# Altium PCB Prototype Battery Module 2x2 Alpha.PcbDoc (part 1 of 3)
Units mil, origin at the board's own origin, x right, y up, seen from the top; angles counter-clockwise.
Board outline 659.45 x 1614.17 mil, 6 copper layers (Component Side, Ground Plane (GND), Inner Layer 1, Inner Layer 2, Power Plane (VCC), Solder Side), stack 51.068 mil thick; 192 components, 101 nets, 859 pads, 497 vias.
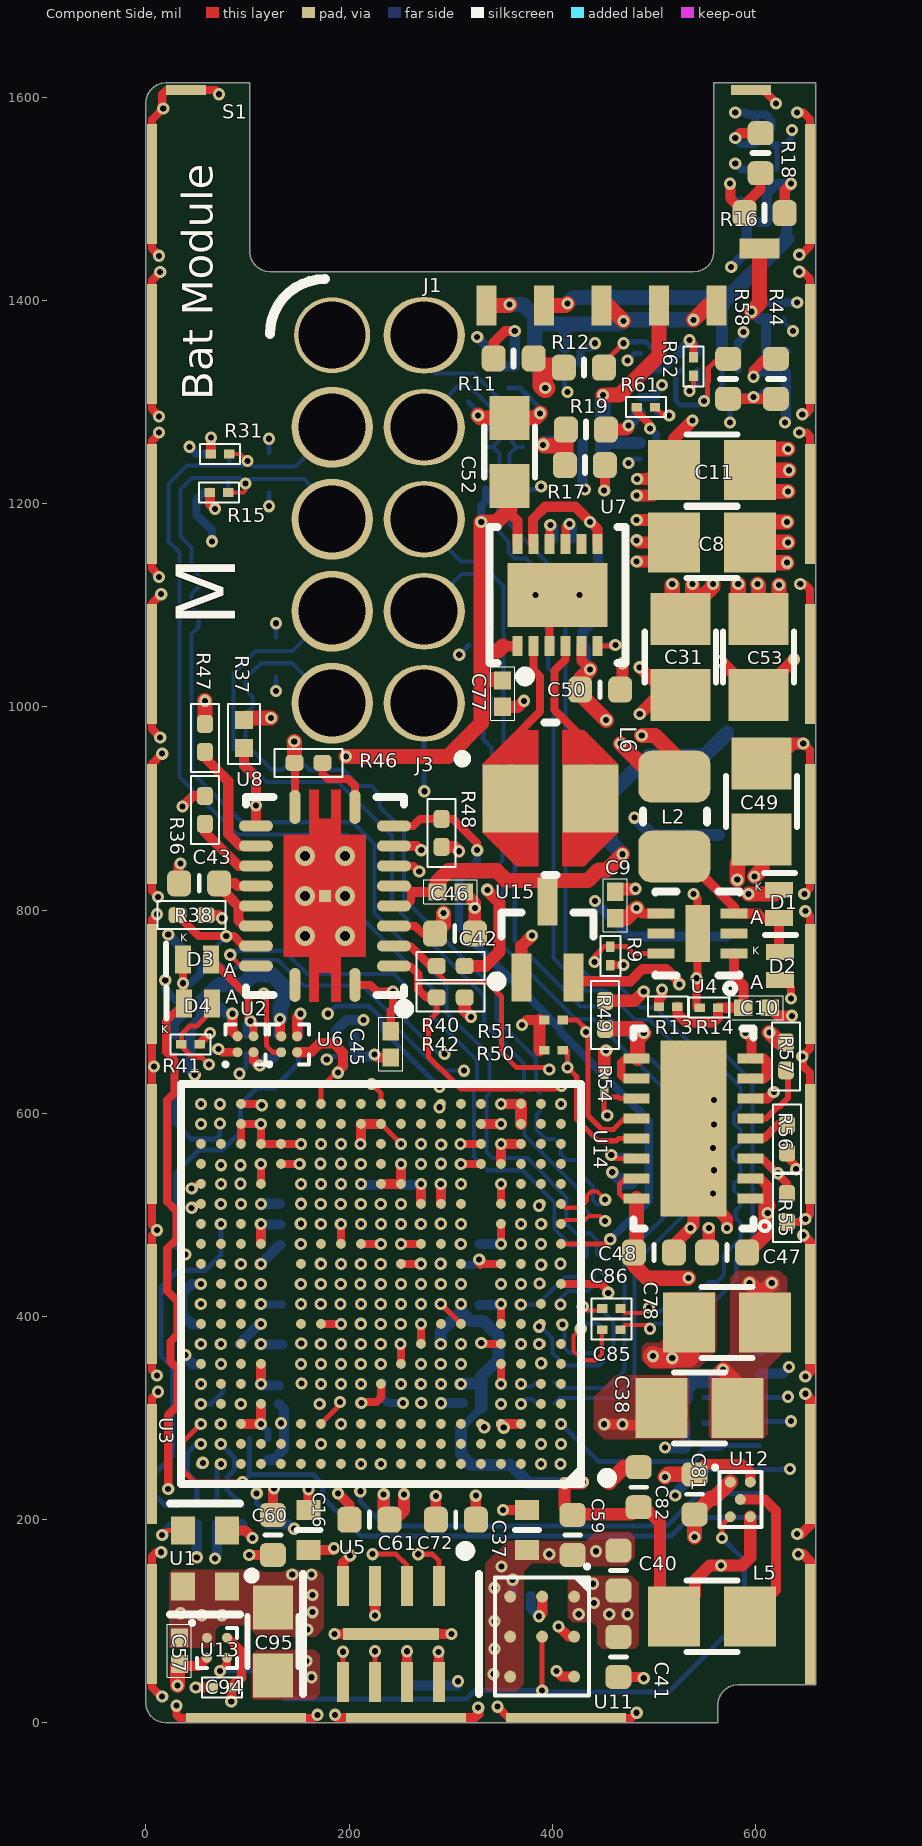
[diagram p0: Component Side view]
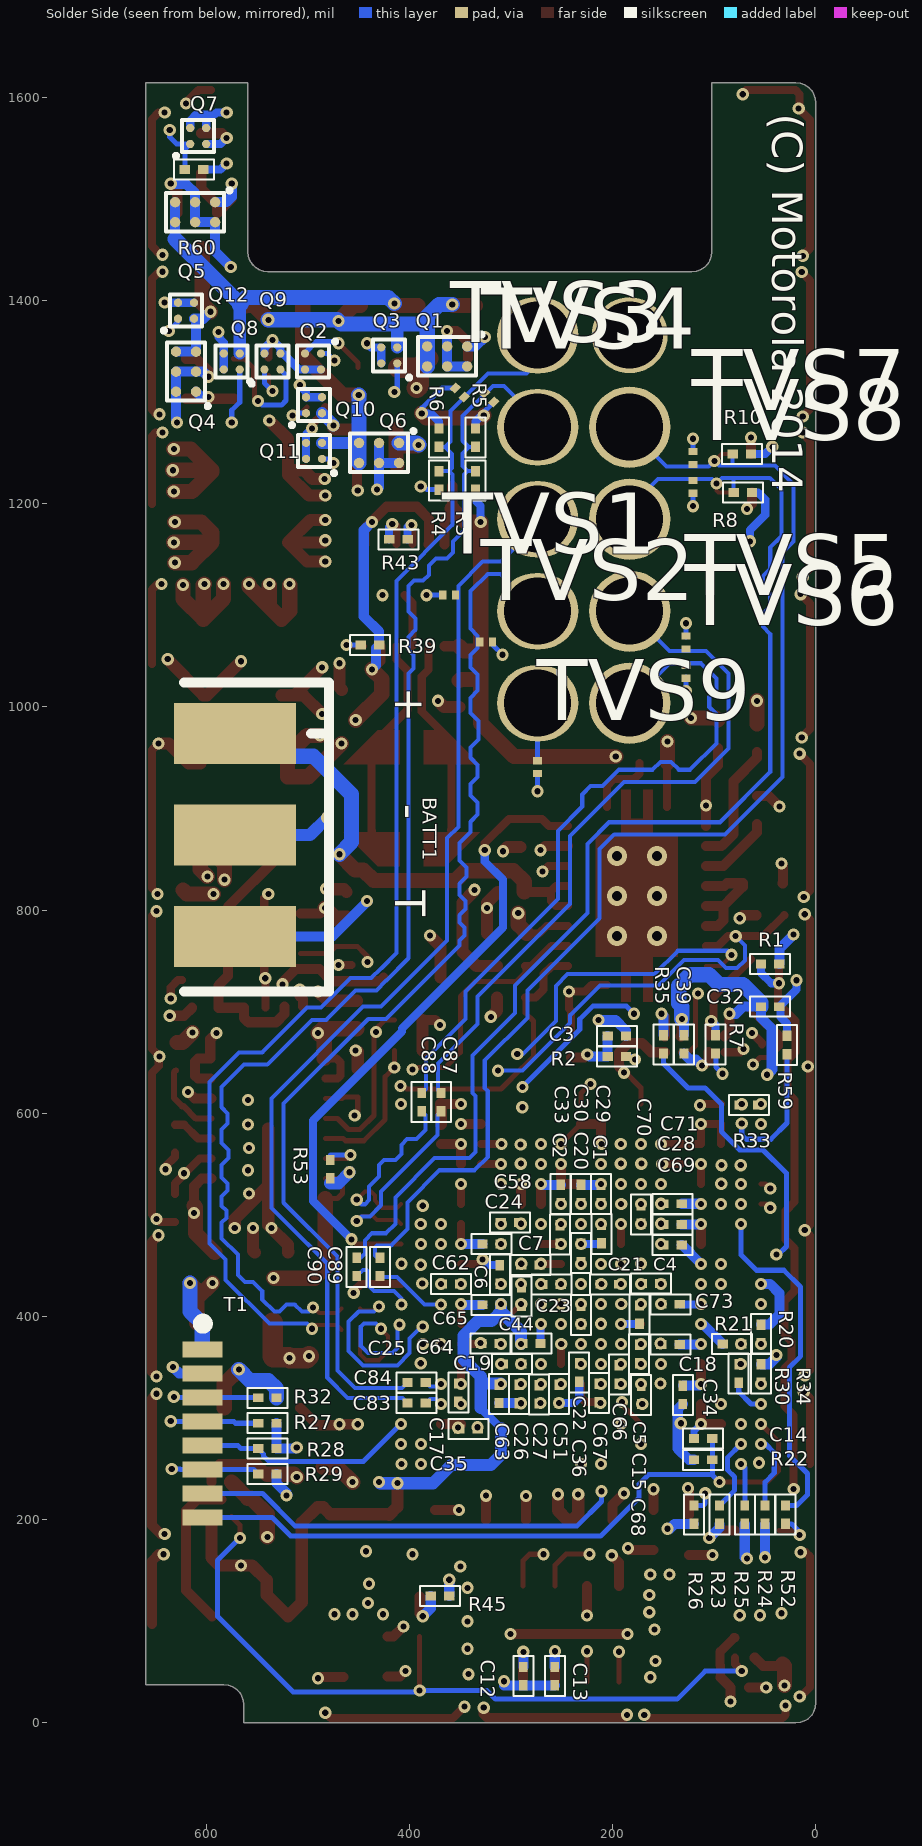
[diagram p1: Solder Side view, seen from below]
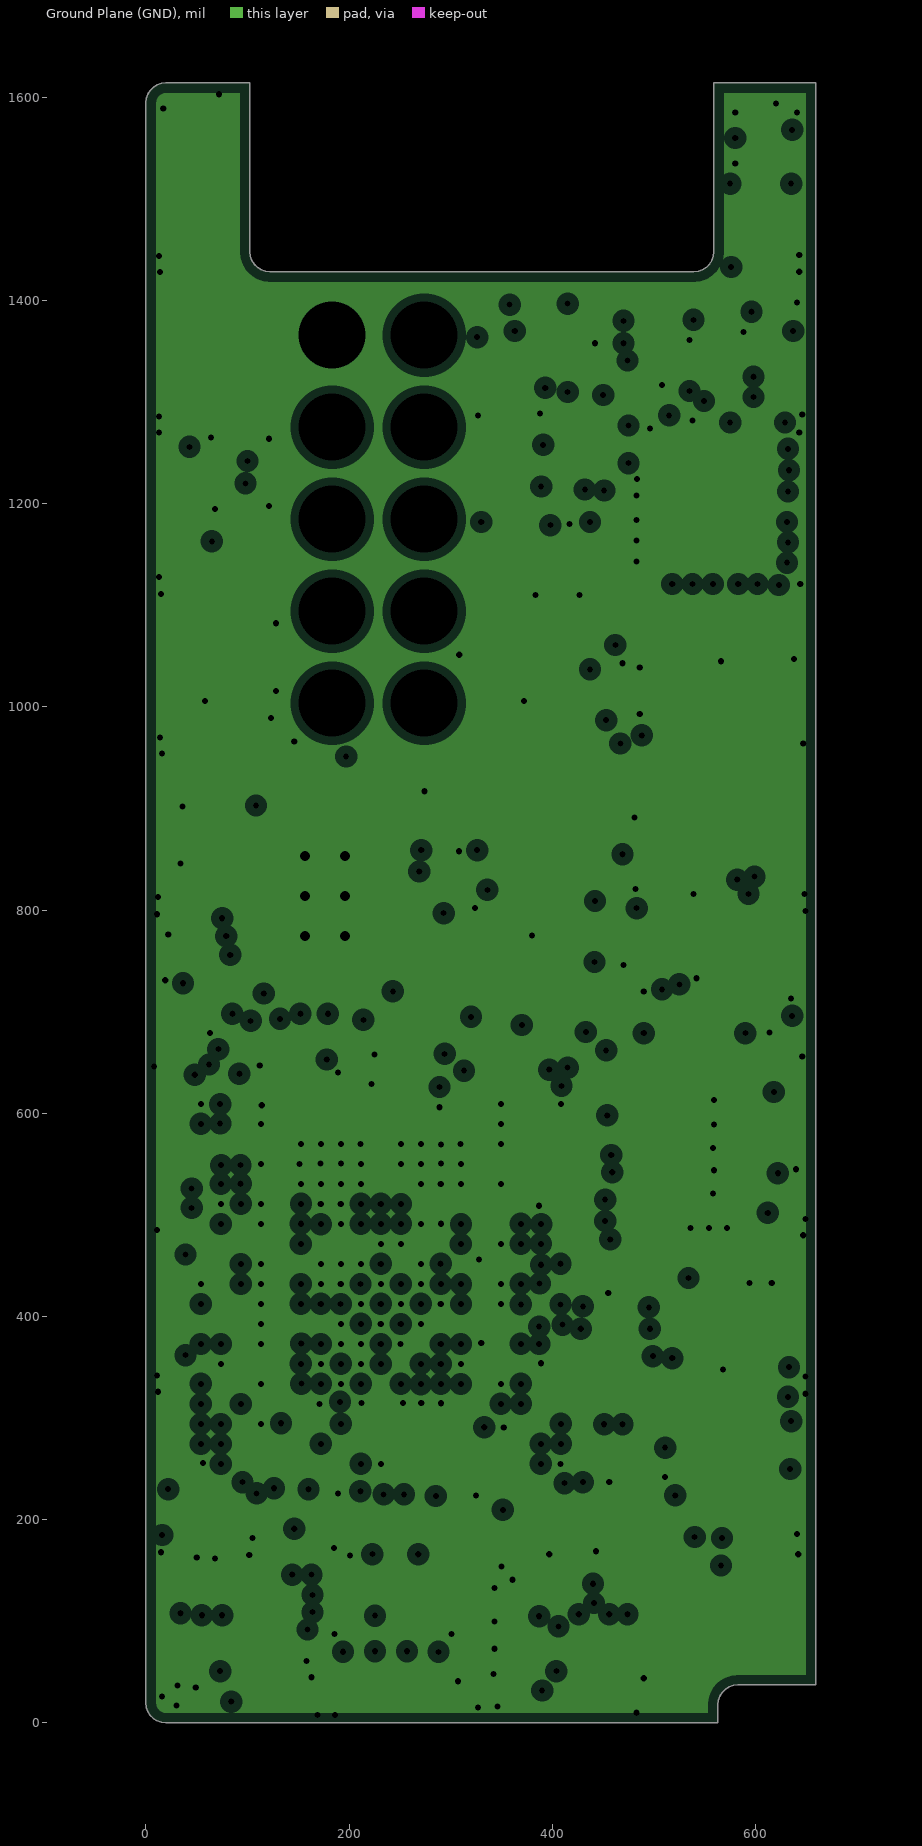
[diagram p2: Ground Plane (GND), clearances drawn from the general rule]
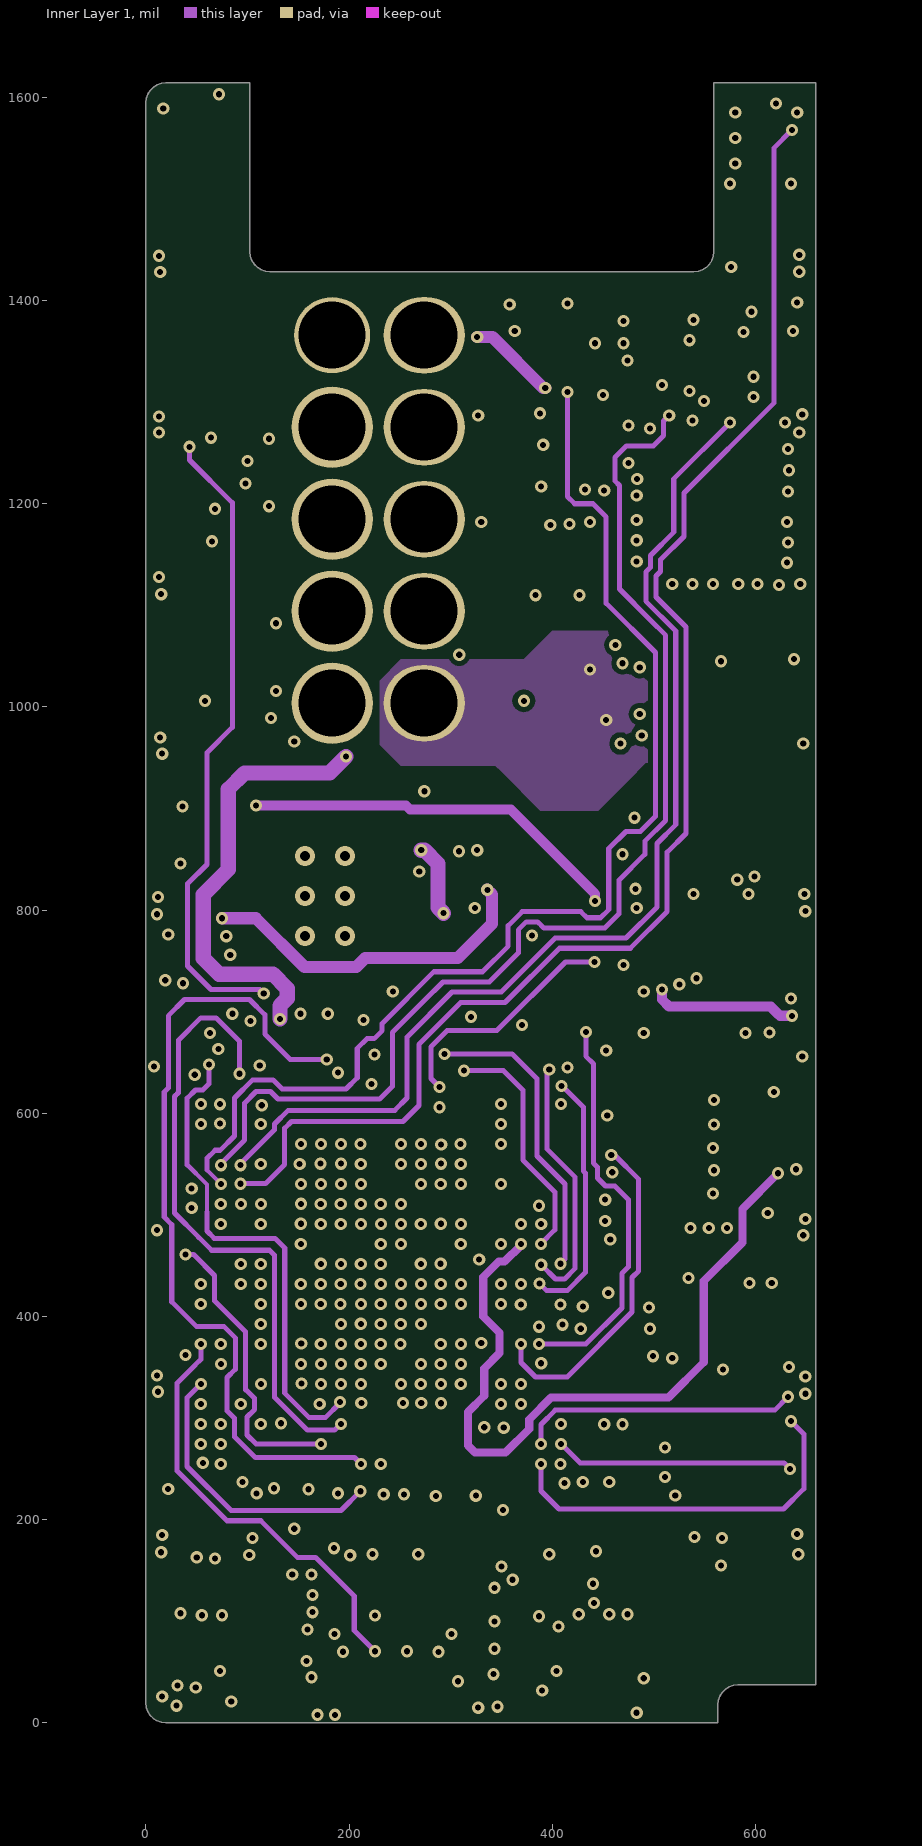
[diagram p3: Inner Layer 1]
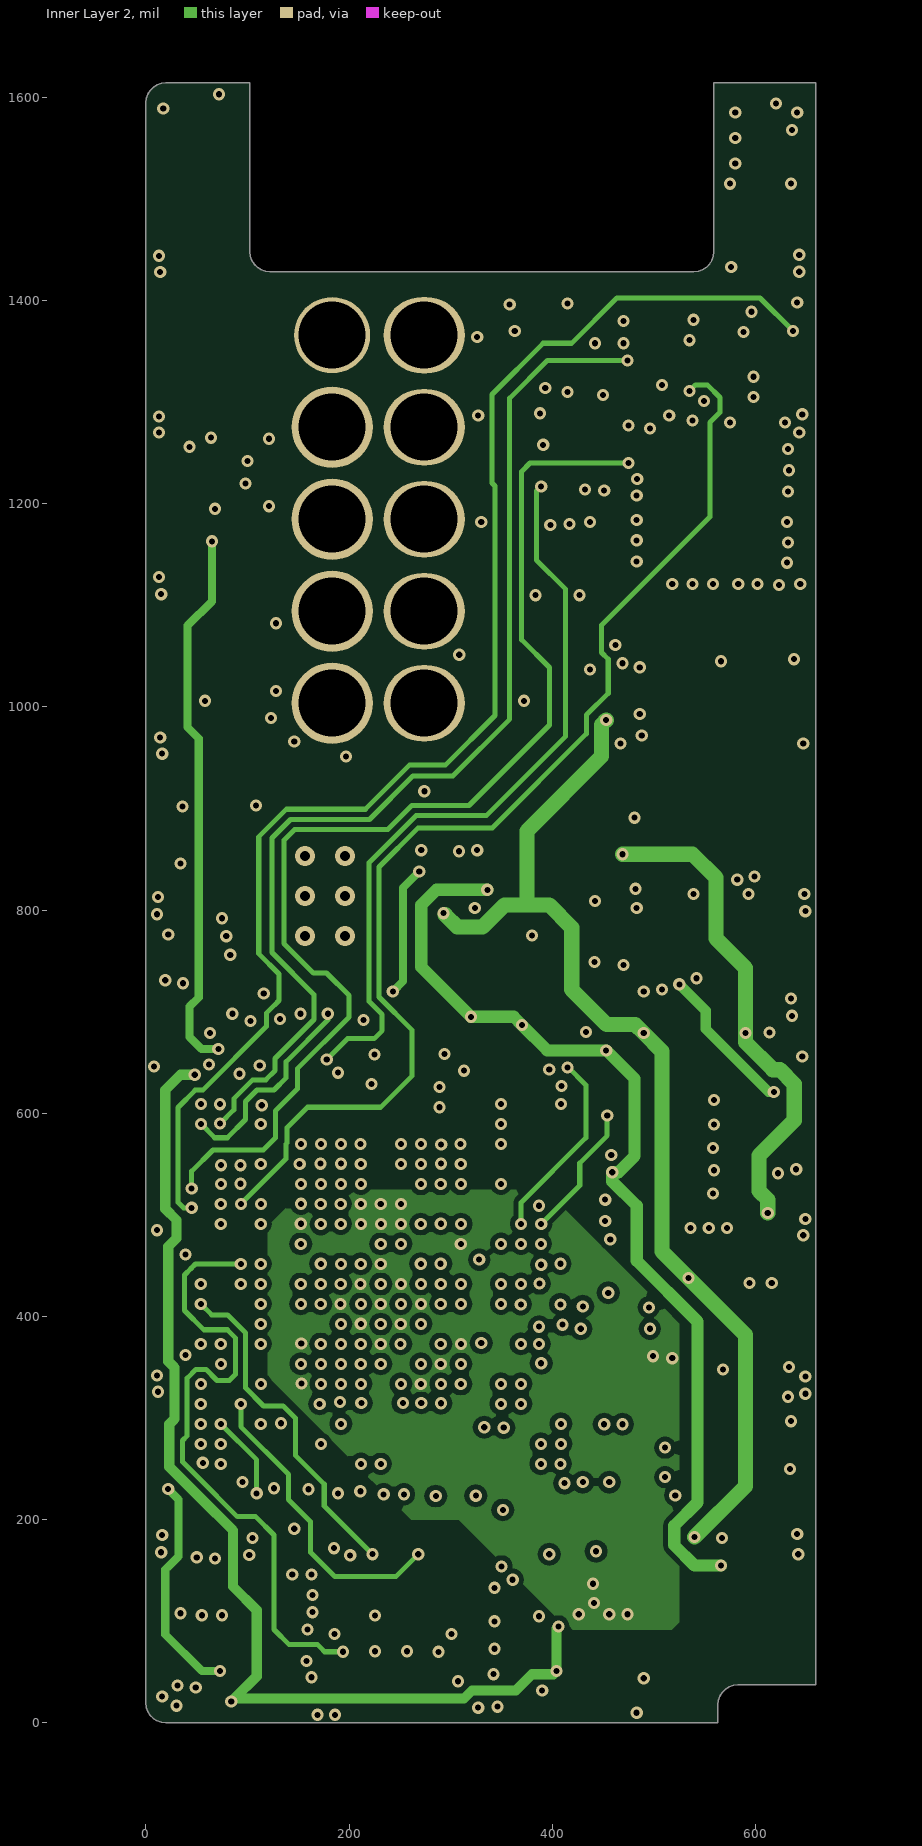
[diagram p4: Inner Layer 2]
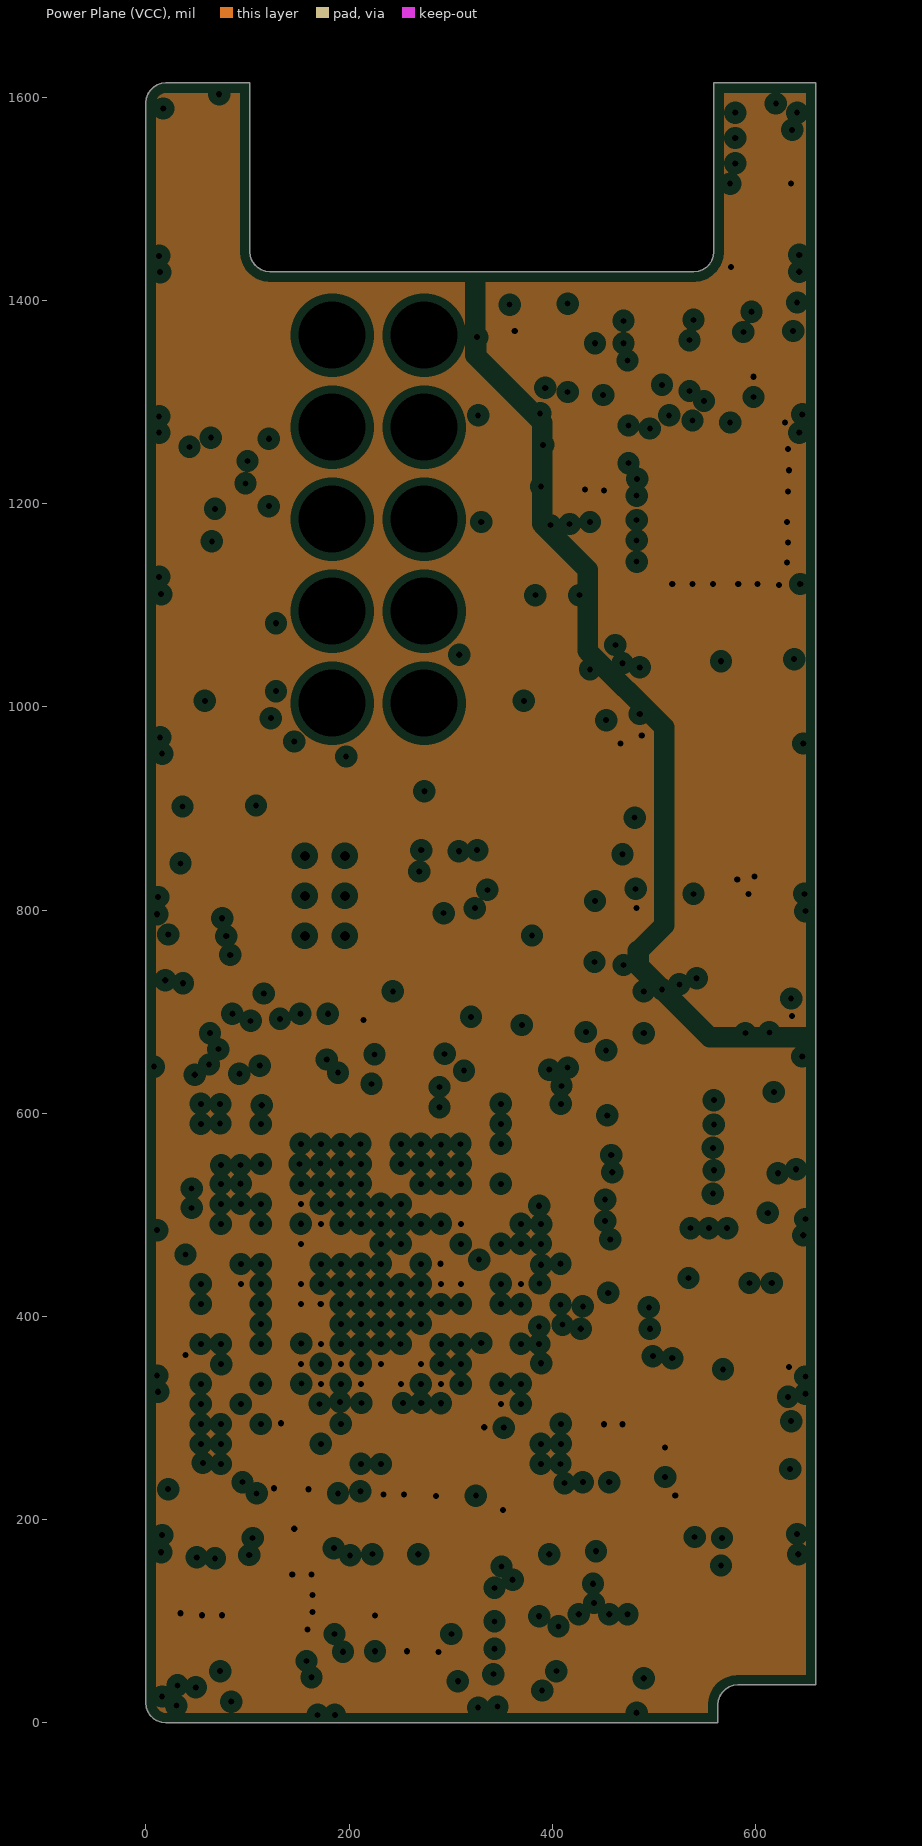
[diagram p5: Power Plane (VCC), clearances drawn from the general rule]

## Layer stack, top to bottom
Top Solder: solder mask 0.4, Solder Resist, Dk 3.5
Component Side: signal copper 1.4
Dielectric1: core 12.6, FR-4, Dk 4.8
Ground Plane (GND): plane copper 1.417, net GND
Dielectric4: prepreg 5, Dk 4.2
Inner Layer 1: signal copper 1.417
Dielectric2: core 10, Dk 4.2
Inner Layer 2: signal copper 1.417
Dielectric3: prepreg 5, Dk 4.2
Power Plane (VCC): plane copper 1.417, net (Multiple Nets)
Dielectric5: core 10, Dk 4.2
Solder Side: signal copper 1.4
Bottom Solder: solder mask 0.4, Solder Resist, Dk 3.5

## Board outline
582.68,37.4 659.45,37.4 659.45,1614.17 559.06,1614.17 559.06,1448.03 558.56,1443.65 557.11,1439.49 554.76,1435.76 551.64,1432.64 547.91,1430.3 543.75,1428.84 539.37,1428.35 122.05,1428.35 117.67,1428.84 113.51,1430.3 109.77,1432.64 106.66,1435.76 104.31,1439.49 102.86,1443.65 102.36,1448.03 102.36,1614.17 19.68,1614.17 15.3,1613.68 11.14,1612.22 7.41,1609.88 4.29,1606.76 1.95,1603.03 0.49,1598.87 0,1594.49 0,19.68 0.49,15.3 1.95,11.14 4.29,7.41 7.41,4.29 11.14,1.95 15.3,0.49 19.68,0 562.99,0 562.99,17.72 563.49,22.1 564.94,26.26 567.29,29.99 570.4,33.11 574.14,35.45 578.3,36.91

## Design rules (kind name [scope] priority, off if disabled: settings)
Clearance diff_1 [InNetClass('diff')] p1: gap=5
Clearance [All] p2: gap=5
DiffPairsRouting [All] p1: maxlimit=8 minlimit=8 mostfreqgap=8 toplayer_minwidth=15 toplayer_maxwidth=15 toplayer_prefwidth=15 midlayer1_minwidth=15 midlayer1_maxwidth=15 midlayer1_prefwidth=15 midlayer2_minwidth=15 midlayer2_maxwidth=15 midlayer2_prefwidth=15 bottomlayer_minwidth=15 bottomlayer_maxwidth=15 bottomlayer_prefwidth=15 maxuncoupledlength=500
FabricationTestPointUsage [All] p1 off: valid=0 allowmultiple=FALSE
FabricationTestpoint [(IsPad And (OnTopLayer Or OnBottomLayer))] p1 off: side=3 testpointundercomponent=TRUE minsize=40 maxsize=100 preferedsize=60 minholesize=0 maxholesize=40 preferedholesize=32 testpointgrid=1 allowsidetop=TRUE allowsidebottom=TRUE usegrid=TRUE gridtolerance=0.01
MatchedLengths DiffPair_MatchedLengths [InDifferentialPair ('SERDES_TX_CHIP')] p1: tolerance=1000 checknetsindiffpair=TRUE checkdiffpairvsdiffpair=TRUE checkothers=TRUE
MatchedLengths DiffPair_MatchedLengths_1 [InDifferentialPair ('SERDES_TX')] p2: tolerance=1000 checknetsindiffpair=TRUE checkdiffpairvsdiffpair=TRUE checkothers=TRUE
MatchedLengths DiffPair_MatchedLengths_2 [InDifferentialPair ('SERDES_RX')] p3: tolerance=1000 checknetsindiffpair=TRUE checkdiffpairvsdiffpair=TRUE checkothers=TRUE
MatchedLengths DiffPair_MatchedLengths_3 [InDifferentialPair ('RCLK_100MHZ')] p4: tolerance=1000 checknetsindiffpair=TRUE checkdiffpairvsdiffpair=TRUE checkothers=TRUE
MatchedLengths DiffPair_MatchedLengths_4 [InDifferentialPair ('OSC_100MHZ')] p5: tolerance=1000 checknetsindiffpair=TRUE checkdiffpairvsdiffpair=TRUE checkothers=TRUE
MinimumSolderMaskSliver [All] p1: minsoldermaskwidth=3
PlaneClearance [All] p1: clearance=8
PlaneConnect [All] p1: planeconnectstyle=Direct reliefexpansion=8 reliefentries=4 reliefconductorwidth=8 reliefairgap=8
PolygonConnect [All] p1: connectstyle=Direct reliefconductorwidth=10 reliefentries=4 polygonreliefangle="90 Angle" airgapwidth=10
RoutingVias [All] p1: holewidth=6 width=12 viastyle="Through Hole" minholewidth=6 minwidth=12 maxholewidth=6 maxwidth=12
SilkToSilkClearance [All] p1: silktosilkclearance=3
SilkToSolderMaskClearance [IsPad] p1: minsilkscreentomaskgap=3 clearancetoexposedcopper=TRUE
SolderMaskExpansion [All] p1: expansion=4
Width diff [InNetClass('diff')] p1: maxlimit=4 minlimit=4 preferedwidth=4
Width [All] p2: maxlimit=30 minlimit=4 preferedwidth=5
21 further rules are at their usual default settings.

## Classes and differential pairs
differential pair TX: +TX_P -TX_N
differential pair TX_CLK: +TX_CLK_P -TX_CLK_N
differential pair RX: +RX_P -RX_N
differential pair RX_CLK: +RX_CLK_P -RX_CLK_N
differential pair C_TX: +C_TX_P -C_TX_N
differential pair C_TX_CLK: +C_TX_CLK_P -C_TX_CLK_N
differential pair C_RX: +C_RX_P -C_RX_N
differential pair C_RX_CLK: +C_RX_CLK_P -C_RX_CLK_N

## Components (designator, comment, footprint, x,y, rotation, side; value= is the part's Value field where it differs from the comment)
BATT1 "J_BATT" 1X3_PADS 571.81,974 r270 bottom
C1 "0.1uF" C_01005 211,481 r90 bottom
C2 "0.1uF" C_01005 251.97,480.71 r90 bottom
C3 "0.1uF" C_01005 196,676 r180 bottom
C4 "0.1uF" C_01005 162.17,432.52 r180 bottom
C5 "0.1uF" C_01005 173.69,401.76 r90 bottom
C6 "0.1uF" C_01005 311.17,441.52 r270 bottom
C7 "0.1uF" C_01005 281.1,450.79 r0 bottom locked
C8 "22µF" C_ERA-0805 557,1162 r0 top
C9 "0.1UF" CAPC0201 462,805 r270 top
C10 "C_0201_22pF" CAPC0201 601,704 r0 top
C11 "22µF" C_ERA-0805 557,1233 r0 top
C12 "0.1uF" C_01005 288,46 r270 bottom
C13 "0.1uF" C_01005 257,46 r270 bottom
C14 "0.1uF" C_01005 111,280 r0 bottom
C15 "0.1uF" C_01005 174,363 r270 bottom
C16 "1.0uF" C_ERA-0402 160,190 r90 top
C17 "0.1uF" C_01005 352,325 r90 bottom
C18 "0.1uF" C_01005 143.17,372.52 r0 bottom
C19 "0.1uF" C_01005 299.24,353.35 r180 bottom
C20 "0.1uF" C_01005 231.17,462.52 r270 bottom
C21 "0.1uF" C_01005 202.69,431.76 r0 bottom
C22 "0.1uF" C_01005 231.17,401.52 r90 bottom
C23 "0.1uF" C_01005 260.17,431.52 r180 bottom
C24 "0.1uF" C_01005 319.17,471.52 r180 bottom
C25 "0.1uF" C_01005 320.17,373.52 r180 bottom
C26 "0.1uF" C_01005 292.32,323.68 r90 bottom
C27 "0.1uF" C_01005 272.55,323.43 r90 bottom
C28 "0.1uF" C_01005 141.17,490.52 r0 bottom
C29 "0.1uF" C_01005 211.67,520.52 r270 bottom
C30 "0.1uF" C_01005 231.17,520.52 r270 bottom
C31 "22µF" C_ERA-0805 526,1049 r90 top
C32 "0.1uF" C_01005 45,705 r0 bottom
C33 "0.1uF" C_01005 251.17,520.52 r270 bottom
C34 "0.1uF" C_01005 131,323 r270 bottom
C35 "0.1uF" C_01005 342.1,289.3 r180 bottom
C36 "0.1uF" C_01005 233,345 r90 bottom
C37 "1.0uF" C_ERA-0402 375,190 r90 top
C38 "22uF" C_ERA-0805 545,310 r180 top
C39 "0.1uF" C_01005 130,668 r90 bottom
C40 "10uF" C_0402 465,150 r270 top
C41 "1uF" C_0402 465,65 r90 top
C42 "C_0402_10uF" C_0402 304,777 r180 top
C43 "C_0402_10uF" C_0402 52.4,826.4 r0 top
C44 "0.1uF" C_01005 289.69,419.76 r90 bottom
C45 "1uF" CAPC0201 241,668 r90 top
C46 "1uF" CAPC0201 300,818 r180 top
C47 "C_0402_10uF" C_0402 572,463 r0 top
C48 "C_0402_10uF" C_0402 500,463 r180 top
C49 "22µF" C_ERA-0805 606,907 r270 top
C50 "10uF" C_0402 447,1017 r180 top
C51 "0.1uF" C_01005 253,324 r90 bottom
C52 "22uF" C_ERA-0603 358,1251 r270 top
C53 "22µF" C_ERA-0805 603,1049 r90 top
C57 "0.47µF" CAPC0201 33,71 r90 top
C58 "0.1uF" C_01005 301.17,492.52 r0 bottom
C59 "10uF" C_0402 420,185 r90 top
C60 "10uF" C_0402 125,185 r90 top
C61 "10uF" C_0402 220,200 r0 top
C62 "0.1uF" C_01005 359,432 r0 bottom
C63 "0.1uF" C_01005 312,324 r90 bottom
C64 "0.1uF" C_01005 280.17,373.52 r0 bottom
C65 "0.1uF" C_01005 319.17,411.52 r180 bottom
C66 "0.1uF" C_01005 194,343 r90 bottom
C67 "0.1uF" C_01005 213.58,324.69 r90 bottom
C68 "0.1uF" C_01005 172,323 r90 bottom
C69 "0.1uF" C_01005 141.17,470.52 r0 bottom
C70 "0.1uF" C_01005 172.17,500.52 r270 bottom
C71 "0.1uF" C_01005 141,511 r0 bottom
C72 "10uF" C_0402 305,200 r180 top
C73 "0.1uF" C_01005 143,412 r0 bottom
C77 "0.47µF" CAPC0201 351,1013 r90 top
C78 "22uF" C_ERA-0805 572,394 r180 top
C81 "4.7uF" C_0402 540,225 r270 top
C82 "10uF" C_0402 485,232 r270 top
C83 "0.1uF" C_01005 393,315 r180 bottom
C84 "0.1uF" C_01005 393,335 r180 bottom
C85 "0.1uF" C_01005 458,387 r180 top
C86 "0.1uF" C_01005 458,408 r180 top
C87 "0.1uF" C_01005 369,611 r270 bottom
C88 "0.1uF" C_01005 388,611 r270 bottom
C89 "0.1uF" C_01005 429,449 r270 bottom
C90 "0.1uF" C_01005 452,449 r270 bottom
C94 "0.1uF" C_01005 75,35 r0 top
C95 "22uF" C_ERA-0603 125,80 r90 top
D1 "SBR0240LP-7" 2-XFDFN 623,806 r270 top
D2 "SBR0240LP-7" 2-XFDFN 624,745 r270 top
D3 "SBR0240LP-7" 2-XFDFN 50.2,751.61 r0 top
D4 "SBR0240LP-7" 2-XFDFN 51,708 r0 top
J1 "EPM" EPM_3X_CONNECTION 335,1395 r90 top
J3 "SPRING PIN" "10PIN SMD CONNECTOR" 273.86,1003.7 r90 top locked
L2 "CBC2016T220K" L_0806 520,892 r90 top
L5 "2.2uH" C_ERA-0805 557,105 r180 top
L6 "2.2uH Wirewound" L_SMD_2.2uH 398,910 r180 top
Q1 "SI8497DB-T2-E1" BGA6C50P3X2_145X96X59 363,1345 r0 bottom
Q2 "SI8808DB-T2-E1" BGA4C40P2X2_80X80X40 495,1340 r0 bottom
Q3 "SI8808DB-T2-E1" BGA4C40P2X2_80X80X40 420,1346 r90 bottom
Q4 "SI8497DB-T2-E1" BGA6C50P3X2_145X96X59 620,1330 r90 bottom
Q5 "SI8497DB-T2-E1" BGA6C50P3X2_145X96X59 611,1487 r0 bottom
Q6 "SI8497DB-T2-E1" BGA6C50P3X2_145X96X59 430,1250 r0 bottom
Q7 "SI8808DB-T2-E1" BGA4C40P2X2_80X80X40 608,1562 r180 bottom
Q8 "SI8808DB-T2-E1" BGA4C40P2X2_80X80X40 575,1340 r90 bottom
Q9 "SI8808DB-T2-E1" BGA4C40P2X2_80X80X40 535,1340 r180 bottom
Q10 "SI8808DB-T2-E1" BGA4C40P2X2_80X80X40 494,1297 r180 bottom
Q11 "SI8808DB-T2-E1" BGA4C40P2X2_80X80X40 494,1252 r90 bottom
Q12 "SI8808DB-T2-E1" BGA4C40P2X2_80X80X40 620,1390 r180 bottom
R1 "1M Ohms" R_01005#1 45,747 r180 bottom
R2 "1k" R_01005#1 196,656 r180 bottom
R3 "10K" R_01005#1 335,1223 r270 bottom
R4 "10K" R_01005#1 371,1223 r270 bottom
R5 "1M Ohms" R_01005#1 335,1265 r90 bottom
R6 "1M Ohms" R_01005#1 371,1265 r90 bottom
R7 "10K" R_01005#1 99,668 r270 bottom
R8 "10K" R_01005#1 71.94,1211 r180 bottom
R9 "1k" R_01005#1 457,755 r270 top
R10 "10K" R_01005#1 72.94,1249 r180 bottom
R11 "270" R_0402 362,1343 r0 top
R12 "100" R_0402 431,1334 r0 top
R13 "10K" R_01005#1 514,705 r0 top
R14 "4.7k" R_01005#1 554,704 r180 top
R15 "1M Ohms" R_01005#1 71.94,1211 r180 top
R16 "270" R_0402 609,1486 r180 top
R17 "270" R_0402 432,1238 r180 top
R18 "100" R_0402 605,1545 r90 top
R19 "100" R_0402 433,1273 r0 top
R20 "1k" R_01005#1 54,383 r270 bottom
R21 "1k" R_01005#1 82.76,373.03 r0 bottom
R22 "10K" R_01005#1 111,259 r180 bottom
R23 "10K" R_01005#1 95,205 r270 bottom
R24 "10K" R_01005#1 50,205 r270 bottom
R25 "10K" R_01005#1 70,205 r270 bottom
R26 "10K" R_01005#1 120,205 r270 bottom
R27 "4.7k" R_01005#1 540,295 r0 bottom
R28 "4.7k" R_01005#1 540,270 r0 bottom
R29 "4.7k" R_01005#1 540,245 r0 bottom
R30 "10K" R_01005#1 76,344 r90 bottom
R31 "1M Ohms" R_01005#1 72.94,1249 r180 top
R32 "4.7k" R_01005#1 540,320 r180 bottom
R33 "10K" R_01005#1 65.91,608.35 r180 bottom
R34 "10K" R_01005#1 54,344 r90 bottom
R35 "10K" R_01005#1 150,668 r270 bottom
R36 "51K" R_0201 58.07,898.62 r90 top
R37 "10K" R0201 96.46,973.43 r90 top
R38 "R_0201_100k" R_0201 45,795 r180 top
R39 "10K" R_01005#1 439,1061 r0 bottom
R40 "R_0201_100k" R_0201 300,745 r180 top
R41 "10K" R_01005#1 44,668 r180 top
R42 "R_0201_100k" R_0201 300,714 r180 top
R43 "10K" R_01005#1 411,1165 r180 bottom
R44 "270" R_0402 620,1323 r270 top
R45 "10K" R_01005#1 370,125 r0 bottom
R46 "3.3K" R_0201 160,945 r180 top
R47 "0 Ohms" R_0201 58.07,969.49 r90 top
R48 "R_0201_100k" R_0201 291,876 r270 top
R49 "R_0201_100k" R_0201 452,697 r90 top
R50 "100K" R_01005#2 401,662 r0 top
R51 "100K" R_01005#2 401,692 r0 top
R52 "33" R_01005#1 30,205 r90 bottom
R53 "100K" R_01005#2 478,545 r90 bottom
R54 "100K" R_01005#2 451,630 r270 top
R55 "R_0201_100k" R_0201 631,507 r270 top
R56 "R_0201_510" R_0201 631,575 r270 top
R57 "1K" R_0201 630,656 r90 top
R58 "100" R_0402 573,1323 r90 top
R59 "1k" R_01005#1 28.54,667.32 r90 bottom
R60 "1k" R_01005#1 612,1529 r180 bottom
R61 "1k" R_01005#1 492,1295 r180 top
R62 "1k" R_01005#1 539,1335 r90 top
S1 "RFSHIELD" RFSHIELD_BATMODULE 0,-0.98 r0 top locked
T1 "8 PIN TEST_INTERFACE" "8-PIN TEST INTERFACE" 604,285 r180 bottom
TVS1 "TVS_ESDAVLC6-1BV2" ST_MICRO_TVS 361,1110 r0 bottom
TVS2 "TVS_ESDAVLC6-1BV2" ST_MICRO_TVS 324.61,1064 r180 bottom
TVS3 "TVS_ESDAVLC6-1BV2" ST_MICRO_TVS 350.55,1309.55 r45 bottom
TVS4 "TVS_ESDAVLC6-1BV2" ST_MICRO_TVS 321.64,1304.64 r225 bottom
TVS5 "TVS_ESDAVLC6-1BV2" ST_MICRO_TVS 128,1063.39 r90 bottom
TVS6 "TVS_ESDAVLC6-1BV2" ST_MICRO_TVS 128,1034.61 r270 bottom
TVS7 "TVS_ESDAVLC6-1BV2" ST_MICRO_TVS 121,1245 r90 bottom
TVS8 "TVS_ESDAVLC6-1BV2" ST_MICRO_TVS 121,1216.61 r270 bottom
TVS9 "TVS_ESDAVLC6-1BV2" ST_MICRO_TVS 273.86,940.75 r270 bottom
U1 "19.2MHz Oscillator" LCCS165P160X200X70-4N 58,162 r90 top
U2 "Buffer" DSBGA4_.4MM 98,668 r0 top
U3 "LFE3-17EA" BGA328C50P19X19_1000X1000X150 231.26,432.17 r180 top locked
U4 "U_LT3460EDC-1" DFN6 543,777 r90 top
U5 "M25P16-VMC6TG" UFDFN8 241.14,87.6 r270 top
U6 "Buffer" DSBGA4_.4MM 141,668 r0 top
U7 "3.3V STEP UP/DOWN" QFN40P300X300X80_HS-13L 405,1110 r0 top
U8 "U_BQ24032ARHLR" RHL20-3050X2050TP 176.18,813.98 r180 top
U11 "TPS82675SIPT" "MICRP SIP" 390,85 r270 top
U12 "2.5V Buck Converter" BGA4C50P2X2_105X138X60 585,220 r270 top
U13 "Power Switch" "DSBGA4 _.5MM" 70,74 r0 top
U14 "U_LTC4415EDHC#PBF" LT-DHC-16_A_V 539,585 r180 top
U15 "TCM810RVLB713" SC70-LB3_N 395,771 r90 top

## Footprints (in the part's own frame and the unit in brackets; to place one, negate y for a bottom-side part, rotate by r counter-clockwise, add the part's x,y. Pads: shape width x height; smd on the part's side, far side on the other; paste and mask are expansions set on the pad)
1X3_PADS [mil]
  rect 60x120 smd mask+0: 1(0,0) 2(100,0) 3(200,0)
  silkscreen extent -50,-50 254,93
2-XFDFN [mm] "2-XFDFN"
  rect 0.4x0.7 smd mask+0: 1(0.35,0) 2(-0.35,0)
  silkscreen extent -0.78,-0.38 -0.78,0.4
"8-PIN TEST INTERFACE" [mm] "SOIC, 4-Leads, Body 3.7x6.0mm (max), Pitch 1.27mm, IPC High Density"
  rect 1x0.4 smd mask+0: 1(0,2.1) 2(0,1.5) 3(0,0.9) 4(0,0.3) 5(0,-0.3) 6(0,-0.9) 7(0,-2.1) 8(0,-1.5)
  silkscreen extent -0.11,2.62 0.14,2.87
"10PIN SMD CONNECTOR" [mil] "10PIN TONKA MODULE CONNECTOR"
  oval 75x80 hole 66 mask+0: 1(0,0) 3(90.55,0) 5(181.1,0) 7(271.65,0) 9(362.2,0)
  round 80 hole 66 mask+0: 2(0,90.55) 4(90.55,90.55) 6(181.1,90.55) 8(271.65,90.55)
  round 74.8 hole 66 mask+0: 10(362.2,90.55)
  silkscreen extent -58,-41 417,152, body extent -36,-36 398,127, height 16
BGA4C40P2X2_80X80X40 [mm] "BGA, 4-Leads, Body 0.80x0.80mmx0.40mm, Pitch 0.40mm"
  round 0.205 smd mask+0: 1(-0.2,-0.2) 2(-0.2,0.2) 3(0.2,0.2) 4(0.2,-0.2)
  silkscreen extent -0.6,-0.55 0.4,0.4, body extent -0.4,-0.4 0.4,0.4, height 0.4
BGA4C50P2X2_105X138X60 [mm] "BGA, 4-Leads, Body 1.05x1.38mmx0.60mm, Pitch 0.50mm"
  round 0.275 smd mask+0: A1(-0.433,-0.25) A3(-0.433,0.25) B2(0,0) C1(0.433,-0.25) C3(0.433,0.25)
  silkscreen extent -0.84,-0.68 0.69,0.53, body extent -0.69,-0.52 0.69,0.53, height 0.6
BGA6C50P3X2_145X96X59 [mm] "BGA, 6-Leads, Body 1.45x0.96mmx0.59mm, Pitch 0.50mm"
  round 0.26 smd mask+0: 1(-0.5,-0.25) 2(-0.5,0.25) 3(0,0.25) 4(0.5,0.25) 5(0.5,-0.25) 6(0,-0.25)
  silkscreen extent -0.91,-0.59 0.72,0.48, body extent -0.72,-0.48 0.72,0.48, height 0.59
BGA328C50P19X19_1000X1000X150 [mm] "BGA, 328-Leads, Body 10.00x10.00mmx1.50mm, Pitch 0.50mm"
  round 0.25 smd mask+0: A1(-4.5,4.5) A2(-4,4.5) A3(-3.5,4.5) A4(-3,4.5) A5(-2.5,4.5) A6(-2,4.5) A7(-1.5,4.5) A8(-1,4.5) A9(-0.5,4.5) A10(0,4.5) A11(0.5,4.5) A12(1,4.5) A13(1.5,4.5) A14(2,4.5) A15(2.5,4.5) A16(3,4.5) A17(3.5,4.5) A18(4,4.5) A19(4.5,4.5) B1(-4.5,4) B2(-4,4) B3(-3.5,4) B4(-3,4) B5(-2.5,4) B6(-2,4) B7(-1.5,4) B8(-1,4) B9(-0.5,4) B10(0,4) B11(0.5,4) B12(1,4) B13(1.5,4) B14(2,4) B15(2.5,4) B16(3,4) B17(3.5,4) B18(4,4) B19(4.5,4) C1(-4.5,3.5) C2(-4,3.5) C3(-3.5,3.5) C4(-3,3.5) C5(-2.5,3.5) C6(-2,3.5) C7(-1.5,3.5) C8(-1,3.5) C9(-0.5,3.5) C10(0,3.5) C11(0.5,3.5) C12(1,3.5) C13(1.5,3.5) C14(2,3.5) C15(2.5,3.5) C16(3,3.5) C17(3.5,3.5) C18(4,3.5) C19(4.5,3.5) D1(-4.5,3) D2(-4,3) D3(-3.5,3) D4(-3,3) D16(3,3) D17(3.5,3) D18(4,3) D19(4.5,3) E1(-4.5,2.5) E2(-4,2.5) E3(-3.5,2.5) E4(-3,2.5) E6(-2,2.5) E7(-1.5,2.5) E8(-1,2.5) E9(-0.5,2.5) E10(0,2.5) E11(0.5,2.5) E12(1,2.5) E13(1.5,2.5) E14(2,2.5) E16(3,2.5) E17(3.5,2.5) E18(4,2.5) E19(4.5,2.5) F1(-4.5,2) F2(-4,2) F3(-3.5,2) F4(-3,2) F6(-2,2) F7(-1.5,2) F8(-1,2) F9(-0.5,2) F10(0,2) F11(0.5,2) F12(1,2) F13(1.5,2) F14(2,2) F16(3,2) F17(3.5,2) F18(4,2) F19(4.5,2) G1(-4.5,1.5) G2(-4,1.5) G3(-3.5,1.5) G4(-3,1.5) G6(-2,1.5) G7(-1.5,1.5) G8(-1,1.5) G9(-0.5,1.5) G10(0,1.5) G11(0.5,1.5) G12(1,1.5) G13(1.5,1.5) G14(2,1.5) G16(3,1.5) G17(3.5,1.5) G18(4,1.5) G19(4.5,1.5) H1(-4.5,1) H2(-4,1) H3(-3.5,1) H4(-3,1) H6(-2,1) H7(-1.5,1) H8(-1,1) H9(-0.5,1) H10(0,1) H11(0.5,1) H12(1,1) H13(1.5,1) H14(2,1) H16(3,1) H17(3.5,1) H18(4,1) H19(4.5,1) J1(-4.5,0.5) J2(-4,0.5) J3(-3.5,0.5) J4(-3,0.5) J6(-2,0.5) J7(-1.5,0.5) J8(-1,0.5) J9(-0.5,0.5) J10(0,0.5) J11(0.5,0.5) J12(1,0.5) J13(1.5,0.5) J14(2,0.5) J16(3,0.5) J17(3.5,0.5) J18(4,0.5) J19(4.5,0.5) K1(-4.5,0) K2(-4,0) K3(-3.5,0) K4(-3,0) K6(-2,0) K7(-1.5,0) K8(-1,0) K9(-0.5,0) K10(0,0) K11(0.5,0) K12(1,0) K13(1.5,0) K14(2,0) K16(3,0) K17(3.5,0) K18(4,0) K19(4.5,0) L1(-4.5,-0.5) L2(-4,-0.5) L3(-3.5,-0.5) L4(-3,-0.5) L6(-2,-0.5) L7(-1.5,-0.5) L8(-1,-0.5) L9(-0.5,-0.5) L10(0,-0.5) L11(0.5,-0.5) L12(1,-0.5) L13(1.5,-0.5) L14(2,-0.5) L16(3,-0.5) L17(3.5,-0.5) L18(4,-0.5) L19(4.5,-0.5) M1(-4.5,-1) M2(-4,-1) M3(-3.5,-1) M4(-3,-1) M6(-2,-1) M7(-1.5,-1) M8(-1,-1) M9(-0.5,-1) M10(0,-1) M11(0.5,-1) M12(1,-1) M13(1.5,-1) M14(2,-1) M16(3,-1) M17(3.5,-1) M18(4,-1) M19(4.5,-1) N1(-4.5,-1.5) N2(-4,-1.5) N3(-3.5,-1.5) N4(-3,-1.5) N6(-2,-1.5) N7(-1.5,-1.5) N8(-1,-1.5) N9(-0.5,-1.5) N10(0,-1.5) N11(0.5,-1.5) N12(1,-1.5) N13(1.5,-1.5) N14(2,-1.5) N16(3,-1.5) N17(3.5,-1.5) N18(4,-1.5) N19(4.5,-1.5) P1(-4.5,-2) P2(-4,-2) P3(-3.5,-2) P4(-3,-2) P6(-2,-2) P7(-1.5,-2) P8(-1,-2) P9(-0.5,-2) P10(0,-2) P11(0.5,-2) P12(1,-2) P13(1.5,-2) P14(2,-2) P16(3,-2) P17(3.5,-2) P18(4,-2) P19(4.5,-2) R1(-4.5,-2.5) R2(-4,-2.5) R3(-3.5,-2.5) R4(-3,-2.5) R6(-2,-2.5) R7(-1.5,-2.5) R8(-1,-2.5) R9(-0.5,-2.5) R10(0,-2.5) R11(0.5,-2.5) R12(1,-2.5) R13(1.5,-2.5) R14(2,-2.5) R16(3,-2.5) R17(3.5,-2.5) R18(4,-2.5) R19(4.5,-2.5) T1(-4.5,-3) T2(-4,-3) T3(-3.5,-3) T4(-3,-3) T5(-2.5,-3) T6(-2,-3) T7(-1.5,-3) T8(-1,-3) T9(-0.5,-3) T10(0,-3) T11(0.5,-3) T12(1,-3) T13(1.5,-3) T14(2,-3) T15(2.5,-3) T16(3,-3) T17(3.5,-3) T18(4,-3) T19(4.5,-3) U1(-4.5,-3.5) U2(-4,-3.5) U3(-3.5,-3.5) U4(-3,-3.5) U5(-2.5,-3.5) U6(-2,-3.5) U7(-1.5,-3.5) U8(-1,-3.5) U9(-0.5,-3.5) U10(0,-3.5) U11(0.5,-3.5) U12(1,-3.5) U13(1.5,-3.5) U14(2,-3.5) U15(2.5,-3.5) U16(3,-3.5) U17(3.5,-3.5) U18(4,-3.5) U19(4.5,-3.5) V1(-4.5,-4) V2(-4,-4) V3(-3.5,-4) V4(-3,-4) V5(-2.5,-4) V6(-2,-4) V7(-1.5,-4) V8(-1,-4) V9(-0.5,-4) V10(0,-4) V11(0.5,-4) V12(1,-4) V13(1.5,-4) V14(2,-4) V15(2.5,-4) V16(3,-4) V17(3.5,-4) V18(4,-4) V19(4.5,-4) W1(-4.5,-4.5) W2(-4,-4.5) W3(-3.5,-4.5) W4(-3,-4.5) W5(-2.5,-4.5) W6(-2,-4.5) W7(-1.5,-4.5) W8(-1,-4.5) W9(-0.5,-4.5) W10(0,-4.5) W11(0.5,-4.5) W12(1,-4.5) W13(1.5,-4.5) W14(2,-4.5) W15(2.5,-4.5) W16(3,-4.5) W17(3.5,-4.5) W18(4,-4.5) W19(4.5,-4.5)
  silkscreen extent -5.78,-5 5,5, body extent -5,-5 5,5, height 1.5
C_0402 [mm] "Capacitor 0402"
  rrect50% 0.6x0.65 smd mask+0: 1(-0.5,0) 2(0.5,0)
  silkscreen extent 0,-0.2 0,0.2, body extent -0.5,-0.3 0.5,0.3, height 0.2
C_01005 [mm] "01005 Capacitor"
  rect 0.26x0.22 smd mask+0: 1(-0.23,0) 2(0.23,0)
  silkscreen extent -0.5,-0.25 0.5,0.25, body extent -0.21,-0.11 0.21,0.11, height 0.22
C_ERA-0402 [mm]
  rect 0.5x0.6 smd mask+0: 1(-0.5,0) 2(0.5,0)
  silkscreen extent 0,-0.3 0,0.3, body extent -0.5,-0.3 0.5,0.3, height 0.2
C_ERA-0603 [mm]
  rect 1.1x1 smd mask+0: 1(-0.85,0) 2(0.85,0)
  silkscreen extent -0.64,-0.64 0.64,0.64, body extent -0.8,-0.4 0.8,0.4, height 0.3
C_ERA-0805 [mm]
  rect 1.3x1.5 smd mask+0: 1(-0.95,0) 2(0.95,0)
  silkscreen extent -0.64,-0.89 0.64,0.89, body extent -0.94,-0.63 1.06,0.63, height 0.78
CAPC0201 [mm] "Chip Capacitor, Body 0.6x0.3mm, Height 0.33mm, IPC Medium Density"
  rect 0.46x0.42 smd mask+0: 1(-0.33,0) 2(0.33,0)
  silkscreen extent -0.66,-0.3 0.67,0.3, body extent -0.31,-0.16 0.32,0.17, height 0.33
DFN6 [mm] "QFN, 6-Leads, Body 2.1x2.1mm (max), Pitch 0.50mm, IPC High Density"
  rect 0.25x0.675 smd mask+0: 1(-0.5,-0.91) 2(0,-0.91) 3(0.5,-0.91) 4(0.5,0.91) 5(0,0.91) 6(-0.5,0.91)
  rect 1.42x0.61 smd mask+0: 7(0,0)
  silkscreen extent -1.5,-1.05 1.05,1.05, body extent -1.05,-1.05 1.05,1.05, height 0.8
"DSBGA4 _.5MM" [mm] "BGA, 4-Leads .5MM Pitch"
  round 0.25 smd mask+0: A1(-0.25,0.25) A2(0.25,0.25) B1(-0.25,-0.25) B2(0.25,-0.25)
  silkscreen extent -0.67,-0.5 0.5,0.67, body extent -0.48,-0.48 0.48,0.48, height 0.6
DSBGA4_.4MM [mm] "BGA, 4-Leads"
  round 0.25 smd mask+0: A1(-0.2,-0.2) A2(-0.2,0.2) B1(0.2,-0.2) B2(0.2,0.2)
  silkscreen extent -0.55,-0.55 0.5,0.5, body extent -0.4,-0.4 0.4,0.4, height 0.5
EPM_3X_CONNECTION [mm] "EPM PAD"
  rect 1x0.5 smd mask+0: 0(0,0) 1(0,-1.44) 2(0,-2.88) 3(0,-4.32) 4(0,-5.76)
  rect 0.5x1 smd mask+0: 5(1.422,-6.833)
  body extent 0.66,-8.18 7.57,0.94, height 2.55
L_0806 [mm] "Inductor 0806"
  rrect50% 1.3x1.8 smd mask+0: 1(1,0) 2(-1,0)
  silkscreen extent -0.15,-0.81 0.15,0.79, body extent -1,-0.63 1,0.62, height 0.78
L_SMD_2.2uH [mm] "Inductor"
  rect 1.4x1.7 smd mask+0: 1(1,0) 2(-1,0)
  Component Side region: -0.3,0.85 -0.3,1.7 -0.85,1.7 -1.7,0.85
  Component Side region: 0.3,0.85 0.3,1.7 0.85,1.7 1.7,0.85
  Component Side region: -0.3,-0.85 -0.3,-1.7 -0.85,-1.7 -1.7,-0.85
  Component Side region: 0.3,-0.85 0.3,-1.7 0.85,-1.7 1.7,-0.85
  silkscreen extent -0.15,-1.9 0.15,1.91, body extent -1.7,-1.7 1.7,1.7, height 1.2
LCCS165P160X200X70-4N [mm]
  rect 0.7x0.6 smd mask+0: 1(-0.7,-0.55) 2(0.7,-0.55) 3(0.7,0.55) 4(-0.7,0.55)
  silkscreen extent -1.4,-1.24 1.38,0.87, body extent -1.05,-0.85 1.05,0.85, height 1.2
LT-DHC-16_A_V [mm] "DHC-16_A, 16-Leads, Body 5x3mm, Pitch 0.5mm, Thermal Pad 4.4x1.65mm"
  rect 0.65x0.25 smd mask+0: 1(-1.425,1.75) 2(-1.425,1.25) 3(-1.425,0.75) 4(-1.425,0.25) 5(-1.425,-0.25) 6(-1.425,-0.75) 7(-1.425,-1.25) 8(-1.425,-1.75) 9(1.425,-1.75) 10(1.425,-1.25) 11(1.425,-0.75) 12(1.425,-0.25) 13(1.425,0.25) 14(1.425,0.75) 15(1.425,1.25) 16(1.425,1.75)
  rect 1.65x4.4 smd mask+0: 17(0,0)
  silkscreen extent -1.91,-2.5 1.5,2.56, body extent -1.5,-2.5 1.5,2.5, height 0.8
"MICRP SIP" [mm]
  round 0.3 smd paste+0.02 mask+0: A1(-1,0.8) A2(0,0.8) A3(1,0.8) B1(-1,0) B2(0,0) C1(-1,-0.8) C2(0,-0.8) C3(1,-0.8)
  silkscreen extent -1.8,-1.17 1.48,1.17, body extent -1.48,-1.17 1.48,1.17, height 1
QFN40P300X300X80_HS-13L [mm] "QFN, 12-Leads, Body 3.00x3.00mm, Pitch 0.40mm, Thermal Pad 2.50x1.60mm, IPC High Density"
  rect 0.25x0.5 smd mask+0: 1(-1,-1.275) 2(-0.6,-1.275) 3(-0.2,-1.275) 4(0.2,-1.275) 5(0.6,-1.275) 6(1,-1.275) 7(1,1.275) 8(0.6,1.275) 9(0.2,1.275) 10(-0.2,1.275) 11(-0.6,1.275) 12(-1,1.275)
  rect 2.5x1.6 smd mask+0: 13(0,0)
  silkscreen extent -1.7,-2.16 1.7,1.7, body extent -1.5,-1.5 1.5,1.5, height 0.8
R0201 [mm] "Chip Resistor, Body 0.6x0.3mm, IPC Medium Density"
  rect 0.45x0.45 smd mask+0: 1(-0.35,0) 2(0.35,0)
  silkscreen extent -0.75,-0.4 0.75,0.4, body extent -0.31,-0.16 0.31,0.16, height 0.3
R_0201 [mm] "Resistor 0201"
  rrect50% 0.45x0.4 smd mask+0: 1(-0.35,0) 2(0.35,0)
  silkscreen extent -0.85,-0.35 0.85,0.35, body extent -0.3,-0.15 0.31,0.16, height 0.29
R_0402 [mm] "Resistor 0402"
  rrect50% 0.6x0.65 smd mask+0: 1(-0.5,0) 2(0.5,0)
  silkscreen extent 0,-0.2 0,0.2, body extent -0.51,-0.25 0.51,0.25, height 0.51
R_01005#1 [mm] "Chip Capacitor, Body 0.4x0.2mm, Height 0.22mm, IPC High Density"
  rect 0.26x0.22 smd mask+0: 1(-0.23,0) 2(0.23,0)
  silkscreen extent -0.5,-0.25 0.5,0.25, body extent -0.21,-0.11 0.21,0.11, height 0.22
R_01005#2 [mm] "Chip Capacitor, Body 0.4x0.2mm, Height 0.22mm, IPC High Density"
  rect 0.26x0.22 smd: 1(-0.23,0) 2(0.23,0)
  body extent -0.21,-0.11 0.21,0.11, height 0.22
RFSHIELD_BATMODULE [mm]
  rect 0.254x3 smd mask+0: S(0.15,2.5) S(0.15,6.5) S(0.15,10.5) S(0.15,14.5) S(0.15,18.5) S(0.15,22.5) S(0.15,26.5) S(0.15,30.5) S(0.15,34.5) S(0.15,38.5) S(16.6,2.5) S(16.6,6.5) S(16.6,10.5) S(16.6,14.5) S(16.6,18.5) S(16.6,22.5) S(16.6,26.5) S(16.6,30.5) S(16.6,34.5) S(16.6,38.5)
  rect 1x0.254 smd mask+0: S(1,40.85) S(15.125,40.85)
  rect 3x0.254 smd mask+0: S(2.5,0.15) S(6.5,0.15) S(10.5,0.15)
RHL20-3050X2050TP [mm] "QFN, 20-Leads, Body 4.5x3.5mm, Pitch 0.5mm, Thermal Pad 3.05x2.05mm, TI Recommended"
  oval 0.28x0.85 smd paste+0 mask+0: 1(-0.75,2.225) 10(-0.75,-2.225) 11(0.75,-2.225) 20(0.75,2.225)
  oval 0.85x0.28 smd paste+0 mask+0: 2(-1.725,1.75) 3(-1.725,1.25) 4(-1.725,0.75) 5(-1.725,0.25) 6(-1.725,-0.25) 7(-1.725,-0.75) 8(-1.725,-1.25) 9(-1.725,-1.75) 12(1.725,-1.75) 13(1.725,-1.25) 14(1.725,-0.75) 15(1.725,-0.25) 16(1.725,0.25) 17(1.725,0.75) 18(1.725,1.25) 19(1.725,1.75)
  rect 0.3x0.3 smd paste-0.15 mask+0: 21(0,0)
  Component Side region: 0.16,2.65 0.16,1.925 -0.16,1.925 -0.16,2.65 -0.39,2.65 -0.39,1.525 -1.025,1.525 -1.025,-1.525 -0.39,-1.525 -0.39,-2.65 -0.16,-2.65 -0.16,-1.925 0.16,-1.925 0.16,-2.65 0.39,-2.65 0.39,-1.525 1.025,-1.525 1.025,1.525 0.39,1.525 0.39,2.65
  silkscreen extent -2.1,-2.48 1.98,2.94, body extent -1.82,-2.33 1.83,2.32, height 1
SC70-LB3_N [mm] "SOT323, 3-Leads, Body 2.0x1.3mm, Pitch 0.65mm, Lead Span 2.1mm, IPC Medium Density"
  rect 1.2x0.5 smd mask+0: 1(-0.95,0.65) 2(-0.95,-0.65) 3(0.95,0)
  silkscreen extent -1.17,-1.15 0.68,1.39, body extent -0.67,-1.12 0.68,1.13, height 1.1
ST_MICRO_TVS [mm] "Chip Capacitor, Body 0.4x0.2mm, Height 0.22mm, IPC High Density"
  rect 0.18x0.225 smd paste-0.225: 1(-0.16,0) 2(0.16,0)
  body extent -0.21,-0.11 0.21,0.11, height 0.22
UFDFN8 [mm]
  rect 1x0.3 smd mask+0: 1(-1.2,1.2) 2(-1.2,0.4) 3(-1.2,-0.4) 4(-1.2,-1.2) 5(1.2,-1.2) 6(1.2,-0.4) 7(1.2,0.4) 8(1.2,1.2)
  rect 0.3x2.4 smd mask+0: 9(0,0)
  silkscreen extent -2.2,-2.2 1.5,2.2, body extent -1.5,-2 1.5,2, height 0.6

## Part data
C1 C2 C3 C4 C5 C6 C7 C12 C13 C14 C15 C17 C18 C19 C20 C21 C22 C23 C24 C25 C26 C27 C28 C29 C30 C32 C33 C34 C35 C36 C39 C44 C51 C58 C62 C63 C64 C65 C66 C67 C68 C69 C70 C71 C73 C83 C84 C85 C86 C87 C88 C89 C90 C94: library part C_01005_0.1uF, "CAP CER 0.1UF 6.3V 20% X5R 01005"
C8 C11 C31 C49 C53: library part C_0805_22µF_35V, "CAP CER 22UF 35V 20% JB 0805"
C9: library part C_0201_0.1UF, "CAP CER 0.1UF 6.3V 10% X5R 0201"
C10: "CAP CER 22PF 50V 5% NP0 0201"
C16 C37: library part C_0402_1.0UF_16V, "CAP CER 1.0UF 16V X5R 0402"
C38 C78: library part C_0805_22UF_6.3V, "CAP CER 22UF 6.3V X7R 10% 0805"
C40 C50 C59 C60 C61 C72 C82: library part C_0402_10uF, "CAP CER 10UF 4V 20% X5R 0402"
C41: library part C_0402_1uF, "CAP CER 1UF 6.3V 20% JB 0402"
C42 C43 C47 C48: "10uF"
C45 C46: library part C_0201_1UF
C52 C95: library part C_0603_22uF, "CAP CER 22UF 6.3V 20% X5R 0603"
C57 C77: library part C_0201_0.47µF, "CAP CER 0.47UF 6.3V 20% JB 0201"
C81: library part C_0402_4.7uF, "CAP CER 4.7UF 6.3V 10% X7R 0603"
D1 D2 D3 D4: library part D_SBR0240LP-7, "DIODE SUP BARRIER 40V 0.25A 2DFN"
J1: library part J_EPM_3_PAD
J3: library part J_TONKA_MODULE_CONNECTOR
L2: library part L_0806_22uH, "INDUCTOR 22UH 10% 0806 SMD"
L5: library part L_0805_2.2uH_160mOhm, "INDUCTOR MULTILAYER 2.2UH 0805"
L6: library part L_SMD_2.2uH, "COIL CHOKE 2.2UH SHIELDED SMD"
Q1 Q4 Q5 Q6: library part Q_PFET_BGA_30V, "MOSFET P-CH D-S 30V MICROFOOT"
Q2 Q3 Q7 Q8 Q9 Q10 Q11 Q12: library part Q_NFET_BGA_30V, "MOSFET N-CH D-S 30V MICROFOOT"
R1 R5 R6 R15 R31: library part R_01005_1M, "RES 1M OHM 1/32W 1% 01005 SMD"
R2 R9 R20 R21 R59 R60 R61 R62: library part R_01005_1k, "RES 1K OHM 1/32W 1% 01005 SM"
R3 R4 R7 R8 R10 R22 R23 R24 R25 R26 R30 R33 R34 R35 R39 R41 R43 R45: library part R_01005_10K, "RES 10K OHM 1/32W 1% 01005"
R11 R16 R17 R44: library part R_0402_270_5%_PW, "RES 270 OHM 1/5W 5% 0402 SMD"
R12 R18 R19 R58: library part R_0402_100_5%_PW, "RES 100 OHM 1/5W 5% 0402 SMD"
R13 R50 R51 R53 R54: library part R_01005_100K, "RES 100K OHM 1/32W 1% 01005 SMD"
R14 R27 R28 R29 R32: library part R_01005_4.7k, "RES 4.7K OHM 1/32W 1% 01005 SMD"
R36: library part R_0201_51K
R37: library part R_0201_10K, "RES 10K OHM 1/20W 1% 0201 SMD"
R46: library part R_0201_3.3K
R47: library part R_0201_0.0
R52: library part R_01005_33, "RES 33 OHM 1/32W 1% 01005"
R56: "510 Ohm"
R57: library part R_0201_1K, "RES 1K OHM 1/20W 1% 0201 SMD"
S1: library part S_RF_SHIELD_BATMODULE
T1: library part TEST_INTERFACE, "8 PIN Test Interface"
TVS1 TVS2 TVS3 TVS4 TVS5 TVS6 TVS7 TVS8 TVS9: "Single Line Bi Trans 8pF"
U1: library part U_ASA-19.200MHZ-L-T, "OSC 19.200 MHZ 3.3V SMD"
U2 U6: library part U_SN74AUP1G34YFPR, "IC BUFFER GATE SGL 4-DSBGA"
U3: library part U_LFE3-17EA-MG328, "IC FPGA 17KLUTS 116I/O 328-BGA"
U4: library part U_LTC3460-1, "IC REG BOOST ADJ 0.18A 6DFN"
U5: library part U_M25P16-VMC6TG, "IC FLASH 16MBIT 75MHZ 8UFDFPN"
U7: library part U_LM3668SD-2833/NOPB, "IC REG BUCK BST SYNC ADJ 12-LLP"
U8: "Dual Input Li-Ion Charger with Dynamic Power Path, Output regulated to 4.4 V, Vbat 4.2 V, 4.3 V, -40 to 85 degC, 20-pin QFN (RHL), Green (RoHS & no Sb/Br)"
U11: library part U_TPS82675SIPT, "IC REG BUCK SYNC 1.2V 0.6A 8USIP"
U12: library part U_LM3671TL-2.5/NOPB, "IC REG BUCK SYNC 2.5V 0.6A 5USMD"
U13: library part U_TPS22913BYZVT, "IC LOAD SWITCH 5V 4DSBGA"
U14: "IC OR CTRLR SRC SELECT 16DFN"
U15: library part U_TCM810RVLB713, "IC RESET MONITOR 2.63V SC70-3"

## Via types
v1: diameter 12, hole 6, Component Side to Solder Side, tented both sides, 490 vias
v2: diameter 19.68, hole 10, Component Side to Solder Side, 6 vias
v3: diameter 12, hole 6, Component Side to Solder Side, 1 vias

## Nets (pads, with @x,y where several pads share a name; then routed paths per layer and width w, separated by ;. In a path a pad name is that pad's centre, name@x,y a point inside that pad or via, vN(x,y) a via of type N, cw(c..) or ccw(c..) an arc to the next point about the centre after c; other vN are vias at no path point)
C_RX_CLK_N: C90.1 J3.6 R8.1 R15.1 TVS8.1 | length 1258.2
  Component Side w4: R15.1@81,1211 95.94,1211 97.95,1213 v1(97.95,1220)
  Solder Side w4: 33.94,1214 34,1214.05 ; R8.1@81,1211 81,1225 ; J3.6@183.31,1184.8 183.31,1196.69 155.5,1224.5 102.45,1224.5 v1(97.95,1220) 92.45,1225.5 45.45,1225.5 34,1214.05 ; C90.1@452,458.06 447.94,458.06 444,462 444,474.97 436.97,482 423,482 414,491 414,517.36 375.36,556 340.97,556 335,561.97 335,617.03 338,620.03 338,656.97 296,698.97 296,725.97 225,796.97 225,865 203.5,886.5 94.5,886.5 45,936 45,1072 52,1079 52,1092 45,1099 45,1111 52,1118 52,1129 45,1136 45,1157 34,1168 34,1214.05
C_RX_CLK_P: C89.1 J3.8 R10.1 R31.1 TVS7.1 | length 1262.2
  Component Side w4: 90.95,1249 R31.1@82,1249 92.95,1249 99.95,1242 v1(100,1242)
  Solder Side w4: R10.1@82,1249 82,1237.56 81.94,1237.5 ; J3.8@183.31,1275.35 183.31,1272.81 147,1236.5 105.5,1236.5 v1(100,1242) 99.95,1242 95.45,1237.5 81.94,1237.5 ; C89.1@429,458.06 432.06,458.06 434,460 434,468 432,470 418.03,470 402,486.03 402,512.38 370.38,544 336,544 323,557 323,622 326,625 326,652 284,694 284,721 213,792 213,860.03 198.53,874.5 89.53,874.5 33,931.03 33,1152.03 22,1163.03 22,1218.92 21.94,1218.97 40.47,1237.5 81.94,1237.5
C_RX_N: C88.1 J3.2 TVS6.1 | length 696.1
  Solder Side w4: J3.2@183.31,1003.7 144.03,1042.97 113,1042.97 98,1027.97 98,1017 105,1010 105,1000 98,993 98,964 123.81,938.2 135,938.2 142.81,946 153.2,946 161,938.2 193.81,938.2 210,922 222,922 230,914 230,902 254,878 254,811 345,720 345,692.97 384,653.97 384,624.05 C88.1@388,620.06
C_RX_P: C87.1 J3.4 TVS5.1 | length 705.2
  Solder Side w4: J3.4@183.31,1094.25 144.03,1054.97 108.03,1054.97 86,1032.94 86,959.03 118.83,926.2 188.83,926.2 242,873.03 242,806.03 333,715.03 333,688 372,649 372,632 ; C87.1@369,620.06 C87.1@372,623.06 ; C87.1@372,623.06 372,632 ; C87.1@372,623.06 372,632
C_TX_CLK_N: C86.1 J3.7 R3.1 R5.1 TVS4.1 | length 1300.6
  Component Side w4: C86.1@467.06,408 471.56,403.5 488.87,403.5 494.37,409 v1(495,409)
  Solder Side w4: J3.7@273.86,1275.35 273.86,1282.86 307,1316 318,1316 347.67,1286.33 347.67,1262 341.61,1255.94 ; R3.1@335,1232.06 342.94,1232.06 ; R5.1@335,1255.94 341.61,1255.94 ; 408.81,744.84 401,752.64 ; v1(495,409) 499,405 506,405 513,412 521,412 528,405 533.03,405 545,416.97 545,425 554,434 562.03,434 569,440.97 569,461 585,477 585,492.38 580.19,497.19 580.19,504.19 585,509 585,518 579,524 579,531 585,537 585,549 578,556 578,564 585,571 585,584 579,590 579,600 585,606 585,626 563,648 540.03,648 496.03,692 482,692 453,721 432.73,721 422.96,730.77 422.88,730.77 401,752.64 ; 341.61,1255.94 348,1249.56 348,1237.11 342.94,1232.06 ; 342.94,1232.06 346.33,1228.67 346.33,1173.7 357.01,1163.01 357.01,1151.99 363,1146 374.03,1146 381,1139.03 381,1130 386.7,1124.3 395.73,1124.3 401,1119.03 401,1094 394,1087 394,1076 401,1069 401,1056 396,1051 396,1038 401,1033 401,752.64
C_TX_CLK_P: C85.1 J3.9 R4.1 R6.1 TVS3.1 | length 1296.9
  Component Side w4: C85.1@467.06,387 471.56,391.5 492.5,391.5 v1(496,388)
  Solder Side w4: J3.9@273.86,1365.9 273.86,1339.14 285,1328 322.97,1328 359.67,1291.3 359.67,1261.33 365.06,1255.94 ; R4.1@369,1232.05 361,1232.05 ; R6.1@371,1255.94 365.06,1255.94 ; 420.81,749.81 413,757.62 ; v1(496,388) 501,393 538,393 581,436 581,456.03 597,472.03 597,630.97 567.97,660 545,660 501,704 486.97,704 457.97,733 437.7,733 427.93,742.77 427.85,742.77 413,757.62 ; 361,1232.05 358,1235.06 358,1248.89 365.06,1255.94 ; 361,1232.05 357.67,1228.72 357.67,1179.33 413,1124 413,757.62
C_TX_N: C84.1 J3.3 TVS2.1 | length 1087.1
  Solder Side w4: J3.3@273.86,1094.25 310.61,1131 323,1131 340,1114 340,1077 333,1070 333,1058 340,1051 340,1039 333,1032 333,1016 340,1009 340,994 332,986 332,968 340,960 340,950 333,943 333,931 340,924 340,913 333,906 333,894 340,887 340,877 351,866 351,849 344,842 344,833 351,826 351,815 345,809 345,801 351,795 351,788 346,783 346,775 351,770 351,765 423,693 440.64,693 524,609.64 524,512 471,459 471,346.97 453.56,329.53 407.53,329.53 C84.1@402.06,335
C_TX_P: C83.1 J3.5 TVS1.1 | length 1086.3
  Solder Side w4: J3.5@273.86,1184.8 273.86,1179.14 310,1143 327.97,1143 352,1118.97 352,881.97 363,870.97 363,769.97 427.97,705 445.62,705 536,614.62 536,507.03 521,492.03 ; C83.1@402.06,315 407.06,320 461,320 481,340 481,452 521,492
CH_EN: R48.1 U3.M1 U8.9 | length 626.3
  Component Side w5: U3.M1@408.43,471.54 452.54,471.54
  Component Side w8: U8.9@244.09,882.88 262.88,882.88 269.78,889.78 R48.1@291,889.78 302.22,889.78 326,866 v1(326,859)
  Solder Side w8: v1(326,859) 326,848 308,830 308,783 407.42,683.58 ; 407.42,680.58 494.87,593.13 494.87,513.87 v1(457,476)
CH_PG: R38.2 U3.M2 U8.18 | length 652.1
  Component Side w8: R38.2@31.22,795 51.83,774.39 v1(79,774.39) 86.58,774.39 96.21,764.77 U8.18@108.26,764.77
  Inner Layer 1 w5: v1(313,642) 352,642 371,623 371,554 402.5,522.5 402.5,485.41 v1@388.74,471.65
  Solder Side w4: v1(79,774.39) 70,765.39 70,750.62 77.62,743 88.38,743 96.38,751 130,751 155,726 212.53,726 242,696.53 242,689 289,642 v1(313,642)
  other v1: 388.74,471.54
